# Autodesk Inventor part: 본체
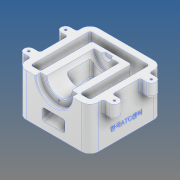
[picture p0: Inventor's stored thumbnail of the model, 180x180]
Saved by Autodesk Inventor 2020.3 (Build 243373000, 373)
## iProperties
Created: 2022-03
Part Number: 본체
Material: 알루미늄 6061
Document SubType Name: Modeling
Designer: EZDESIGN
Density: 2.7 g/cm^3
Appearance: 알루미늄 - 평지
Mass: 1024.19 g
Surface Area: 846.218 cm^2
Volume: 379.331 cm^3
Author: EZDESIGN
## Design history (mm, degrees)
sketch "스케치1"
  geometry: L1 (55, 55)-(-55, 55); L2 (-55, 55)-(-55, -55); L3 (-55, -55)-(55, -55); L4 (55, -55)-(55, 55); L5 (55, 55)-(-55, -55); L6 (-55, 55)-(55, -55); 1 further point
  constraints: 12 end point, 2 midpoint, 2 parallel, 1 horizontal, 1 perpendicular
  dimensions: "d0" = 110 distance of L3.end L2.end; "d1" = 110 distance of L2.end L1.end
extrude "돌출1" new body sketch "스케치1" distance "d2" = 65; taper "d3" = 0 deg
fillet "모깎기1" dims "d4" = 13
sketch "스케치2"
  geometry: L1 (-45, 45)-(-45, -45); L2 (-45, -45)-(-30, -45); L3 (-30, -45)-(-30, 33); L4 (-30, 33)-(30, 33); L5 (30, 33)-(30, -45); L6 (30, -45)-(45, -45); L7 (45, -45)-(45, 45); L8 (45, 45)-(-45, 45); L9 (42, 55)-(-42, 55) reference; L10 (-55, 42)-(-55, -42) reference; L11 (-42, -55)-(42, -55) reference; L12 (55, -42)-(55, 42) reference; A1 r 13 centre (42, 42) between (55, 42) and (42, 55) reference; A2 r 13 centre (-42, 42) between (-42, 55) and (-55, 42) reference; A3 r 13 centre (-42, -42) between (-55, -42) and (-42, -55) reference; A4 r 13 centre (42, -42) between (42, -55) and (55, -42) reference; 1 further point
  constraints: 16 end point, 6 perpendicular, 2 point on line, 1 vertical
  dimensions: "d5" = 10 distance between parallel lines of L8 L9; "d6" = 10 distance between parallel lines of L12 L7; "d7" = 10 distance between parallel lines of L10 L1; "d8" = 10 distance between parallel lines of L11 L2; "d9" = 60 distance of L3.end L4.end; "d10" = 30 distance from line of point (0, 0) L5; "d11" = 22 distance between parallel lines of L4 L9
extrude "돌출2" cut sketch "스케치2" distance "d12" = 65; taper "d13" = 0 deg
sketch "스케치3"
  geometry: L1 (14, 65)-(70, 65); L2 (0, 0)-(84, 0) reference; L3 (0, 65)-(84, 65) reference; A1 r 28 centre (42, 65) between (14, 65) and (70, 65); 3 further points
  constraints: 2 end point, 2 midpoint, 2 point on circle, 1 centre point, 1 collinear, 1 horizontal, 1 horizontal alignment, 1 vertical alignment
  dimensions: "d14" = 56 diameter of A1
extrude "돌출3" cut sketch "스케치3" distance "d15" = 8; taper "d16" = 0 deg
sketch "스케치4"
  geometry: L1 (14, 65)-(70, 65) reference; L2 (23, 65)-(61, 65); A1 r 28 centre (42, 65) between (14, 65) and (70, 65) reference; A2 r 19 centre (42, 65) between (23, 65) and (61, 65); 1 further point
  constraints: 2 end point, 2 point on circle, 2 point on line, 1 centre point, 1 coincident
  dimensions: "d17" = 38 diameter of A2
extrude "돌출4" cut sketch "스케치4" distance "d18" = 72; taper "d19" = 0 deg
sketch "스케치5"
  geometry: L1 (23, 65)-(61, 65) reference; C1 r 7.5 at (42, 65); A1 r 19 centre (42, 65) between (23, 65) and (61, 65) reference; 1 further point
  constraints: 1 centre point, 1 coincident
  dimensions: "d20" = 15 diameter of C1
extrude "돌출5" cut sketch "스케치5" distance "d21" = 4; taper "d22" = -30 deg
sketch "스케치6" dims "d23" = 46
  geometry: L1 (14, 65)-(23, 65) reference; L2 (61, 65)-(70, 65) reference; A1 r 19 centre (42, 65) between (23, 65) and (61, 65) reference; A2 r 28 centre (42, 65) between (14, 65) and (70, 65) reference; 3 further points
  constraints: 2 vertical alignment, 1 coincident, 2 other
hole "구멍1" sketch "스케치6" at (42, 42) diameter "d24" = 3.242; stored, may be unused: countersink angle "d28" = 90 deg, drill point angle "d30" = 118 deg; dims "d25" = 9, "d26" = 4, "d27" = 2, "d29" = 11
sketch "스케치8"
  geometry: L1 (78, 0)-(0, 0) reference; L2 (78, 0)-(78, -65) reference; L3 (0, -65)-(78, -65) reference; L4 (0, 0)-(0, -65) reference; L5 (0, -65)-(78, -65); L6 (78, -35)-(0, -55.9); L7 (0, -65)-(0, -55.9); L8 (78, -35)-(78, -65); 1 further point
  constraints: 8 end point, 2 collinear, 2 point on line, 1 vertical
  dimensions: "d32" = 30 distance of L2.end L6.start; "d33" = 75 deg angle of L6 L2
extrude "돌출6" cut sketch "스케치8" distance "d34" = 60; taper "d35" = 0 deg
sketch "스케치9"
  geometry: L1 (29.197, 55)-(11.597, 55); L2 (11.597, 55)-(31.425, -19); L3 (31.425, -19)-(74.362, -19); L4 (74.362, -19)-(74.362, 19); L5 (74.362, 19)-(38.843, 19); L6 (38.843, 19)-(29.197, 55); L7 (0, 55)-(65, 55) reference; L8 (30, -33)-(9.1, 45) reference; 1 further point
  constraints: 12 end point, 3 parallel, 2 perpendicular, 1 collinear, 1 horizontal
  dimensions: "d37" = 17 distance between parallel lines of L2 L6; "d38" = 38 distance between parallel lines of L3 L5; "d39" = 36 distance between parallel lines of L5 L7; "d40" = 5 distance between parallel lines of L8 L2; "d41" = 42.93694 distance from line of L2.end L4
extrude "돌출7" cut sketch "스케치9" stored distance "d42" = 34; taper "d43" = 0 deg
sketch "스케치10"
  geometry: L1 (54, 28)-(65, 28); L2 (54, 21)-(65, 21); L3 (65, 35)-(54, 35); L4 (55, -42)-(55, 42) reference; L5 (42, 55)-(-42, 55) reference; A1 r 7 centre (54, 28) between (54, 35) and (54, 21); A2 r 7 centre (65, 28) between (65, 21) and (65, 35); 4 further points
  constraints: 8 end point, 4 point on circle, 4 tangent, 2 centre point, 1 horizontal, 1 midpoint, 1 parallel
  dimensions: "d44" = 14 diameter of A2; "d45" = 27 vertical distance of point (59.5, 28) L5.start; "d46" = 10 horizontal distance of L1.end L4.end; "d47" = 1 distance from line of L4 L3.end
extrude "돌출8" join sketch "스케치10" distance "d48" = 20; taper "d49" = 0 deg
sketch "스케치11"
  geometry: A1 r 7 centre (65, 28) between (65, 21) and (65, 35) reference; 3 further points
  constraints: 1 coincident
hole "구멍2" sketch "스케치11" at (65, 28), (82.881, 81.093) diameter "d50" = 3.242; stored, may be unused: countersink angle "d54" = 90 deg, drill point angle "d56" = 118 deg; dims "d51" = 9, "d52" = 4, "d53" = 2, "d55" = 11
fillet "모깎기2" dims "d57" = 1
fillet "모깎기3" dims "d58" = 3
fillet "모깎기4" dims "d59" = 3
fillet "모깎기5" dims "d60" = 3
fillet "모깎기6" dims "d61" = 3
fillet "모깎기7" dims "d62" = 3
fillet "모깎기8" dims "d63" = 3
fillet "모깎기9" dims "d64" = 3
fillet "모깎기10" dims "d65" = 3
node "작업 평면1"
sketch "스케치12"
  geometry: L1 (-13, 65)-(-13, 0) reference; 2 further points
  constraints: 1 other
  dimensions: "d67" = 20 distance of point (42, 0) point (42, 20); "d68" = 55 distance from line of point (42, 20) L1
feature "엠보싱1" sketch "스케치12" dims "d0" = 110, "d1" = 110, "d69" = 0.5, "d70" = 0
chamfer "모따기1" distance "d71" = 1; stored, may be unused: second distance "d72" = 2, angle "d73" = 45 deg
node "솔리드1"
mirror "미러1"
mirror "미러2"
node "투영된 루프1"
node "투영된 루프2"
node "투영된 루프3"
node "투영된 루프4"
node "투영된 루프6"
feature "A9D066F2-1C7D-4E18-AEED-F7BC21143FA4" dims "d50" = 3.242, "d51" = 9, "d52" = 4, "d53" = 2, "d54" = 90 deg, "d55" = 11, "d56" = 118 deg
other parameters: "d66" = 5
